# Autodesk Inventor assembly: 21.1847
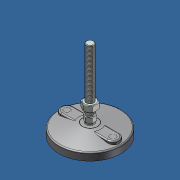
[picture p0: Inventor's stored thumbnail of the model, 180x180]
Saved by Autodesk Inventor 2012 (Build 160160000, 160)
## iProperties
Created: 2007-03
Part Number: 21.1847
Document SubType Name: Assembly
Designer: Andy Moles
Description: LEVELING FOOT M12 WITH ATTACHMENT BORES
Author: Andy Moles
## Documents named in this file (5)
- C:\Andys Backup Data\ANDY'S INVENTOR\INVENTOR LIBRARIES\PARTS LIBRARY\FEET WHEELS FLOOR FASTENING SUPPORTS\21.1847 LEVELING FOOT M12 WITH BORES.iam
- C:\Andys Backup Data\ANDY'S INVENTOR\INVENTOR LIBRARIES\PARTS LIBRARY\FASTENING ELEMENTS\NUTS\21.1528 M12 HEX NUT.ipt
- C:\Andys Backup Data\ANDY'S INVENTOR\INVENTOR LIBRARIES\PARTS LIBRARY\FEET WHEELS FLOOR FASTENING SUPPORTS\SUBCOMPONENTS\LEVELING FEET SUBCOMPONENTS\PAD 100mm GRAY PLASTIC WITH BORES.IPT
- C:\Andys Backup Data\ANDY'S INVENTOR\INVENTOR LIBRARIES\PARTS LIBRARY\FEET WHEELS FLOOR FASTENING SUPPORTS\SUBCOMPONENTS\LEVELING FEET SUBCOMPONENTS\ANTI-SKID PAD 100mm WITH BORES.ipt
- C:\Andys Backup Data\ANDY'S INVENTOR\INVENTOR LIBRARIES\PARTS LIBRARY\FEET WHEELS FLOOR FASTENING SUPPORTS\SUBCOMPONENTS\LEVELING FEET SUBCOMPONENTS\THREADED STUD 12mm 100mm THREAD.ipt
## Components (4 placed, 4 different names)
1. ANTI-SKID PAD 100mm WITH BORES:1 — Insert:1, Mate:4
2. PAD 100mm GRAY PLASTIC WITH BORES:1 — Insert:1, Tangent:1, Mate:1, Mate:4
3. THREADED STUD 12mm 100mm THREAD:1 — Tangent:1, Mate:1, Mate:2
4. 21.1528 M12 HEX NUT:1 — Mate:2
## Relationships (5: Mate 3, Insert 1, Tangent 1)
- Insert:1: ANTI-SKID PAD 100mm WITH BORES:1 ↔ PAD 100mm GRAY PLASTIC WITH BORES:1
- Tangent:1: PAD 100mm GRAY PLASTIC WITH BORES:1 ↔ THREADED STUD 12mm 100mm THREAD:1
- Mate:1: PAD 100mm GRAY PLASTIC WITH BORES:1 ↔ THREADED STUD 12mm 100mm THREAD:1
- Mate:2: THREADED STUD 12mm 100mm THREAD:1 ↔ 21.1528 M12 HEX NUT:1
- Mate:4: ANTI-SKID PAD 100mm WITH BORES:1 ↔ PAD 100mm GRAY PLASTIC WITH BORES:1
